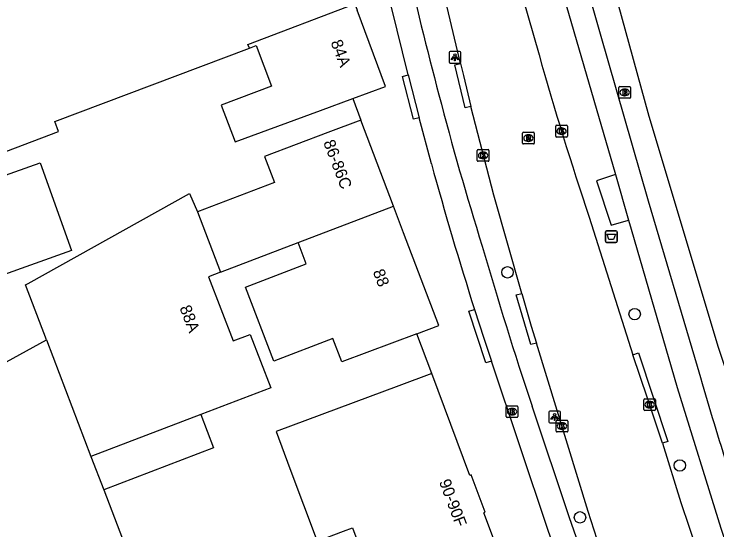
# Model space of a CAD drawing. Extents: x 160026 to 161302, y 384757 to 385701.
# Drawn here: x 160779.8 to 160839.9, y 384906.6 to 384950.7 of the extents above; entities that cross this region are included whole.
import ezdxf

# ---------------------------------------------------------------- set-up
doc = ezdxf.new("R2010")
doc.units = 0
for name, color, linetype in [('IMGEO_Afvalbak', 7, 'Continuous'), ('IMGEO_Boom', 7, 'Continuous'), ('IMGEO_Brandkraan', 7, 'Continuous'), ('IMGEO_Fietspad_open', 7, 'Continuous'), ('IMGEO_Kolk', 7, 'Continuous'), ('IMGEO_Lichtpunt', 7, 'Continuous'), ('IMGEO_Pand', 7, 'Continuous'), ('IMGEO_Pand_nummerreeks', 7, 'Continuous'), ('IMGEO_Rijbaan_lokaal_gesloten', 7, 'Continuous'), ('IMGEO_Rioolput', 7, 'Continuous'), ('IMGEO_Voetpad_gesloten', 7, 'Continuous'), ('IMGEO_Voetpad_open', 7, 'Continuous')]:
    doc.layers.add(name, color=color, linetype=linetype)

msp = doc.modelspace()

# ---------------------------------------------------------------- linework, layer by layer
at = {"layer": 'IMGEO_Afvalbak'}
for p, q in [((160830.469, 384932.145), (160831.259, 384932.145)), ((160831.259, 384932.145), (160830.469, 384932.145)), ((160830.369, 384931.245), (160830.369, 384932.045)), ((160830.369, 384932.045), (160830.369, 384931.245)), ((160831.359, 384932.045), (160831.359, 384931.245)), ((160831.359, 384931.245), (160831.359, 384932.045)), ((160831.259, 384931.145), (160830.469, 384931.145)), ((160830.469, 384931.145), (160831.259, 384931.145))]:
    msp.add_line(p, q, dxfattribs=at)
msp.add_lwpolyline([(160830.512, 384931.859), (160831.216, 384931.859), (160831.067, 384931.389), (160830.661, 384931.389), (160830.512, 384931.859)], dxfattribs=at)
for centre, start, end in [((160830.469, 384932.045), 90, 180), ((160830.469, 384932.045), 90, 180), ((160831.259, 384932.045), 0, 90), ((160831.259, 384932.045), 360, 90), ((160830.469, 384931.245), 180, 270), ((160830.469, 384931.245), 180, 270), ((160831.259, 384931.245), 270, 0), ((160831.259, 384931.245), 270, 0)]:
    msp.add_arc(centre, 0.1, start, end, dxfattribs=at)
at = {"layer": 'IMGEO_Boom'}
for centre in [(160821.994, 384928.592), (160832.87, 384925.019), (160836.726, 384912.075), (160828.191, 384907.632)]:
    msp.add_circle(centre, 0.489, dxfattribs=at)
at = {"layer": 'IMGEO_Brandkraan'}
for p, q in [((160831.513, 384943.548), (160831.513, 384944.4)), ((160831.588, 384944.474), (160832.44, 384944.474)), ((160832.001, 384944.254), (160832.026, 384944.254)), ((160832.514, 384944.4), (160832.514, 384943.548)), ((160832.024, 384943.694), (160831.999, 384943.694)), ((160832.44, 384943.474), (160831.588, 384943.474)), ((160821.884, 384916.248), (160821.884, 384917.1)), ((160821.959, 384917.174), (160822.811, 384917.174)), ((160822.885, 384917.1), (160822.885, 384916.248)), ((160822.372, 384916.954), (160822.397, 384916.954)), ((160822.811, 384916.174), (160821.959, 384916.174)), ((160822.395, 384916.394), (160822.37, 384916.394))]:
    msp.add_line(p, q, dxfattribs=at)
for points in [[(160831.513, 384943.548), (160831.513, 384944.4)], [(160831.588, 384944.474), (160832.44, 384944.474)], [(160831.861, 384944.174), (160831.861, 384943.774), (160832.074, 384943.774)], [(160832.092, 384944.174), (160831.861, 384944.174)], [(160832.514, 384944.4), (160832.514, 384943.548)], [(160832.04, 384944.093), (160831.986, 384944.093), (160831.986, 384944.017)], [(160831.986, 384944.017), (160832.039, 384944.017)], [(160832.048, 384943.941), (160831.986, 384943.941), (160831.986, 384943.86)], [(160831.986, 384943.86), (160832.048, 384943.86)], [(160832.44, 384943.474), (160831.588, 384943.474)], [(160821.884, 384916.248), (160821.884, 384917.1)], [(160821.959, 384917.174), (160822.811, 384917.174)], [(160822.885, 384917.1), (160822.885, 384916.248)], [(160822.232, 384916.874), (160822.232, 384916.474), (160822.445, 384916.474)], [(160822.463, 384916.874), (160822.232, 384916.874)], [(160822.411, 384916.793), (160822.357, 384916.793), (160822.357, 384916.717)], [(160822.357, 384916.717), (160822.41, 384916.717)], [(160822.419, 384916.641), (160822.357, 384916.641), (160822.357, 384916.56)], [(160822.357, 384916.56), (160822.419, 384916.56)], [(160822.811, 384916.174), (160821.959, 384916.174)]]:
    msp.add_lwpolyline(points, dxfattribs=at)
for centre, radius, start, end in [((160831.59, 384944.398), 0.0765, 91.55205, 178.44795), ((160831.59, 384944.398), 0.0765, 91.55205, 178.44795), ((160832.096, 384944.029), 0.145, 59.4692, 91.53667), ((160832.121, 384944.076), 0.0922, 285.51372, 58.15012), ((160832.438, 384944.398), 0.0765, 1.55205, 88.44795), ((160832.438, 384944.398), 0.0765, 1.55205, 88.44795), ((160831.59, 384943.55), 0.0765, 181.55205, 268.44795), ((160831.59, 384943.55), 0.0765, 181.55205, 268.44795), ((160832.041, 384944.055), 0.0379, 267.82845, 90.93552), ((160832.049, 384943.9), 0.0404, 269.87594, 90.50774), ((160832.08, 384944.025), 0.251, 268.66757, 293.53466), ((160832.126, 384943.884), 0.105, 301.31148, 78.98903), ((160832.438, 384943.55), 0.0765, 271.55205, 358.44795), ((160832.438, 384943.55), 0.0765, 271.55205, 358.44795), ((160821.961, 384917.098), 0.0765, 91.55205, 178.44795), ((160821.961, 384917.098), 0.0765, 91.55205, 178.44795), ((160822.809, 384917.098), 0.0765, 1.55205, 88.44795), ((160822.809, 384917.098), 0.0765, 1.55205, 88.44795), ((160822.412, 384916.755), 0.0379, 267.82845, 90.93552), ((160822.42, 384916.6), 0.0404, 269.87594, 90.50774), ((160822.451, 384916.725), 0.251, 268.66757, 293.53466), ((160822.467, 384916.729), 0.145, 59.4692, 91.53667), ((160822.492, 384916.776), 0.0922, 285.51372, 58.15012), ((160822.497, 384916.584), 0.105, 301.31148, 78.98903), ((160821.961, 384916.25), 0.0765, 181.55205, 268.44795), ((160821.961, 384916.25), 0.0765, 181.55205, 268.44795), ((160822.809, 384916.25), 0.0765, 271.55205, 358.44795), ((160822.809, 384916.25), 0.0765, 271.55205, 358.44795)]:
    msp.add_arc(centre, radius, start, end, dxfattribs=at)
for centre, major_axis, ratio, start_param, end_param in [((160832, 384943.974), (-0.387, 0.002), 0.722429, 4.712389, 7.853982), ((160832.025, 384943.974), (-0.39, 0.002), 0.717154, 1.570796, 4.712389), ((160822.371, 384916.674), (-0.387, 0.002), 0.722429, 4.712389, 7.853982), ((160822.396, 384916.674), (-0.39, 0.002), 0.717154, 1.570796, 4.712389)]:
    msp.add_ellipse(centre, major_axis=major_axis, ratio=ratio, start_param=start_param, end_param=end_param, dxfattribs=at)
at = {"layer": 'IMGEO_Fietspad_open'}
for points in [[(160814.194, 385007.048), (160814.986, 385000), (160815.844, 384994.219), (160816.431, 384990.383), (160816.702, 384988.921), (160817.127, 384986.92), (160817.62, 384984.728), (160818.538, 384981.595), (160820.892, 384972.809), (160823.521, 384963.563), (160825.943, 384955.094), (160829.383, 384943.326), (160831.218, 384936.953)], [(160813.512, 384945.476), (160812.075, 384951.268), (160810.742, 384956.99), (160809.406, 384962.711), (160806.711, 384974.852), (160805.938, 384978.422), (160804.898, 384983.229)], [(160822.229, 384975.915), (160826.033, 384962.616), (160829.91, 384948.986), (160834.021, 384934.719), (160838.209, 384920.565)], [(160813.512, 384945.476), (160814.451, 384941.818)], [(160815.496, 384937.862), (160814.451, 384941.818)], [(160831.218, 384936.953), (160832.341, 384933.054)], [(160832.341, 384933.054), (160832.563, 384932.283), (160836.504, 384918.732), (160840.233, 384906.719), (160842.877, 384898.87), (160846.129, 384889.655), (160847.192, 384886.516)], [(160819.177, 384925.414), (160819.968, 384922.959), (160820.618, 384920.998)], [(160826.184, 384904.475), (160825.468, 384906.506), (160820.618, 384920.998)], [(160836.248, 384882.034), (160827.287, 384907.585), (160824.095, 384917.15)]]:
    msp.add_lwpolyline(points, dxfattribs=at)
for centre, radius, start, end in [((161146.831, 385031.365), 342.1, 192.79581, 194.83349), ((161076.974, 385011.413), 269.467, 194.53522, 197.39997), ((161127.862, 385023.463), 323.883, 195.32523, 197.62173), ((161158.101, 385028.576), 352.102, 196.11702, 198.44886), ((161097.911, 384994.45), 270.008, 195.88097, 199.34259)]:
    msp.add_arc(centre, radius, start, end, dxfattribs=at)
at = {"layer": 'IMGEO_Kolk'}
for p, q in [((160826.19, 384941.165), (160827.042, 384941.165)), ((160826.115, 384940.239), (160826.115, 384941.091)), ((160826.603, 384940.945), (160826.628, 384940.945)), ((160827.116, 384941.091), (160827.116, 384940.239)), ((160827.042, 384940.165), (160826.19, 384940.165)), ((160826.626, 384940.385), (160826.601, 384940.385)), ((160819.408, 384938.161), (160819.408, 384939.013)), ((160819.483, 384939.087), (160820.335, 384939.087)), ((160819.896, 384938.867), (160819.921, 384938.867)), ((160820.409, 384939.013), (160820.409, 384938.161)), ((160819.919, 384938.307), (160819.894, 384938.307)), ((160820.335, 384938.087), (160819.483, 384938.087)), ((160833.647, 384916.845), (160833.647, 384917.697)), ((160833.722, 384917.771), (160834.574, 384917.771)), ((160834.648, 384917.697), (160834.648, 384916.845)), ((160834.135, 384917.551), (160834.16, 384917.551)), ((160834.574, 384916.771), (160833.722, 384916.771)), ((160834.158, 384916.991), (160834.133, 384916.991)), ((160826.231, 384915.936), (160827.083, 384915.936)), ((160826.156, 384915.01), (160826.156, 384915.862)), ((160826.644, 384915.716), (160826.669, 384915.716)), ((160827.157, 384915.862), (160827.157, 384915.01)), ((160827.083, 384914.936), (160826.231, 384914.936)), ((160826.667, 384915.156), (160826.642, 384915.156))]:
    msp.add_line(p, q, dxfattribs=at)
for points in [[(160826.19, 384941.165), (160827.042, 384941.165)], [(160826.115, 384940.239), (160826.115, 384941.091)], [(160826.436, 384940.865), (160826.559, 384940.865), (160826.559, 384940.714), (160826.689, 384940.865), (160826.853, 384940.865), (160826.707, 384940.714), (160826.86, 384940.465), (160826.708, 384940.465), (160826.623, 384940.629), (160826.559, 384940.562), (160826.559, 384940.465), (160826.436, 384940.465), (160826.436, 384940.865)], [(160827.116, 384941.091), (160827.116, 384940.239)], [(160827.042, 384940.165), (160826.19, 384940.165)], [(160819.408, 384938.161), (160819.408, 384939.013)], [(160819.483, 384939.087), (160820.335, 384939.087)], [(160819.729, 384938.787), (160819.852, 384938.787), (160819.852, 384938.636), (160819.982, 384938.787), (160820.146, 384938.787), (160820, 384938.636), (160820.153, 384938.387), (160820.001, 384938.387), (160819.916, 384938.551), (160819.852, 384938.484), (160819.852, 384938.387), (160819.729, 384938.387), (160819.729, 384938.787)], [(160820.409, 384939.013), (160820.409, 384938.161)], [(160820.335, 384938.087), (160819.483, 384938.087)], [(160833.647, 384916.845), (160833.647, 384917.697)], [(160833.722, 384917.771), (160834.574, 384917.771)], [(160834.648, 384917.697), (160834.648, 384916.845)], [(160833.968, 384917.471), (160834.091, 384917.471), (160834.091, 384917.32), (160834.221, 384917.471), (160834.385, 384917.471), (160834.239, 384917.32), (160834.392, 384917.071), (160834.24, 384917.071), (160834.155, 384917.235), (160834.091, 384917.168), (160834.091, 384917.071), (160833.968, 384917.071), (160833.968, 384917.471)], [(160834.574, 384916.771), (160833.722, 384916.771)], [(160826.231, 384915.936), (160827.083, 384915.936)], [(160826.156, 384915.01), (160826.156, 384915.862)], [(160826.477, 384915.636), (160826.6, 384915.636), (160826.6, 384915.485), (160826.73, 384915.636), (160826.894, 384915.636), (160826.748, 384915.485), (160826.901, 384915.236), (160826.749, 384915.236), (160826.664, 384915.4), (160826.6, 384915.333), (160826.6, 384915.236), (160826.477, 384915.236), (160826.477, 384915.636)], [(160827.157, 384915.862), (160827.157, 384915.01)], [(160827.083, 384914.936), (160826.231, 384914.936)]]:
    msp.add_lwpolyline(points, dxfattribs=at)
for centre, start, end in [((160826.192, 384941.089), 91.55205, 178.44795), ((160826.192, 384941.089), 91.55205, 178.44795), ((160827.04, 384941.089), 1.55205, 88.44795), ((160827.04, 384941.089), 1.55205, 88.44795), ((160826.192, 384940.241), 181.55205, 268.44795), ((160826.192, 384940.241), 181.55205, 268.44795), ((160827.04, 384940.241), 271.55205, 358.44795), ((160827.04, 384940.241), 271.55205, 358.44795), ((160819.485, 384939.011), 91.55205, 178.44795), ((160819.485, 384939.011), 91.55205, 178.44795), ((160820.333, 384939.011), 1.55205, 88.44795), ((160820.333, 384939.011), 1.55205, 88.44795), ((160819.485, 384938.163), 181.55205, 268.44795), ((160819.485, 384938.163), 181.55205, 268.44795), ((160820.333, 384938.163), 271.55205, 358.44795), ((160820.333, 384938.163), 271.55205, 358.44795), ((160833.724, 384917.695), 91.55205, 178.44795), ((160833.724, 384917.695), 91.55205, 178.44795), ((160834.572, 384917.695), 1.55205, 88.44795), ((160834.572, 384917.695), 1.55205, 88.44795), ((160833.724, 384916.847), 181.55205, 268.44795), ((160833.724, 384916.847), 181.55205, 268.44795), ((160834.572, 384916.847), 271.55205, 358.44795), ((160834.572, 384916.847), 271.55205, 358.44795), ((160826.233, 384915.86), 91.55205, 178.44795), ((160826.233, 384915.86), 91.55205, 178.44795), ((160827.081, 384915.86), 1.55205, 88.44795), ((160827.081, 384915.86), 1.55205, 88.44795), ((160826.233, 384915.012), 181.55205, 268.44795), ((160826.233, 384915.012), 181.55205, 268.44795), ((160827.081, 384915.012), 271.55205, 358.44795), ((160827.081, 384915.012), 271.55205, 358.44795)]:
    msp.add_arc(centre, 0.0765, start, end, dxfattribs=at)
for centre, major_axis, ratio, start_param, end_param in [((160826.602, 384940.665), (-0.387, 0.002), 0.722429, 4.712389, 7.853982), ((160826.627, 384940.665), (-0.39, 0.002), 0.717154, 1.570796, 4.712389), ((160819.895, 384938.587), (-0.387, 0.002), 0.722429, 4.712389, 7.853982), ((160819.92, 384938.587), (-0.39, 0.002), 0.717154, 1.570796, 4.712389), ((160834.134, 384917.271), (-0.387, 0.002), 0.722429, 4.712389, 7.853982), ((160834.159, 384917.271), (-0.39, 0.002), 0.717154, 1.570796, 4.712389), ((160826.643, 384915.436), (-0.387, 0.002), 0.722429, 4.712389, 7.853982), ((160826.668, 384915.436), (-0.39, 0.002), 0.717154, 1.570796, 4.712389)]:
    msp.add_ellipse(centre, major_axis=major_axis, ratio=ratio, start_param=start_param, end_param=end_param, dxfattribs=at)
at = {"layer": 'IMGEO_Lichtpunt'}
for p, q in [((160816.998, 384947.387), (160816.998, 384946.58)), ((160816.998, 384947.387), (160816.998, 384946.58)), ((160817.9, 384947.482), (160817.092, 384947.482)), ((160817.9, 384947.482), (160817.092, 384947.482)), ((160817.994, 384946.58), (160817.994, 384947.387)), ((160817.994, 384946.58), (160817.994, 384947.387)), ((160817.092, 384946.486), (160817.9, 384946.486)), ((160817.092, 384946.486), (160817.9, 384946.486)), ((160825.525, 384916.617), (160825.525, 384915.81)), ((160825.525, 384916.617), (160825.525, 384915.81)), ((160826.427, 384916.712), (160825.619, 384916.712)), ((160826.427, 384916.712), (160825.619, 384916.712)), ((160826.521, 384915.81), (160826.521, 384916.617)), ((160826.521, 384915.81), (160826.521, 384916.617)), ((160825.619, 384915.716), (160826.427, 384915.716)), ((160825.619, 384915.716), (160826.427, 384915.716))]:
    msp.add_line(p, q, dxfattribs=at)
for points in [[(160817.372, 384947.051), (160817.411, 384947.023), (160817.223, 384946.761), (160817.185, 384946.788), (160817.372, 384947.051)], [(160817.474, 384947.003), (160817.521, 384947.003), (160817.521, 384946.681), (160817.474, 384946.681), (160817.474, 384947.003)], [(160817.584, 384947.023), (160817.622, 384947.05), (160817.809, 384946.788), (160817.77, 384946.76), (160817.584, 384947.023)], [(160825.899, 384916.281), (160825.938, 384916.253), (160825.75, 384915.991), (160825.712, 384916.018), (160825.899, 384916.281)], [(160826.001, 384916.233), (160826.048, 384916.233), (160826.048, 384915.911), (160826.001, 384915.911), (160826.001, 384916.233)], [(160826.111, 384916.253), (160826.149, 384916.28), (160826.336, 384916.018), (160826.297, 384915.99), (160826.111, 384916.253)]]:
    msp.add_lwpolyline(points, dxfattribs=at)
for centre in [(160817.497, 384947.185), (160826.024, 384916.415)]:
    msp.add_circle(centre, 0.0994, dxfattribs=at)
for centre, start, end in [((160817.092, 384947.387), 90, 180), ((160817.092, 384947.387), 90, 180), ((160817.9, 384947.387), 0, 90), ((160817.9, 384947.387), 0, 90), ((160817.092, 384946.58), 180, 270), ((160817.092, 384946.58), 180, 270), ((160817.9, 384946.58), 270, 0), ((160817.9, 384946.58), 270, 360), ((160825.619, 384916.617), 90, 180), ((160825.619, 384916.617), 90, 180), ((160826.427, 384916.617), 0, 90), ((160826.427, 384916.617), 0, 90), ((160825.619, 384915.81), 180, 270), ((160825.619, 384915.81), 180, 270), ((160826.427, 384915.81), 270, 0), ((160826.427, 384915.81), 270, 360)]:
    msp.add_arc(centre, 0.0946, start, end, dxfattribs=at)
at = {"layer": 'IMGEO_Pand'}
for points in [[(160771.783, 384953.899), (160777.651, 384938.371), (160783.627, 384940.629), (160783.304, 384941.484), (160799.934, 384947.768)], [(160799.934, 384947.768), (160799.812, 384948.089), (160808.95, 384951.552), (160809.153, 384951.006)], [(160808.778, 384943.448), (160811.572, 384944.473), (160809.153, 384951.006)], [(160784.732, 384930.464), (160775.379, 384927.123), (160776.271, 384924.625), (160770.071, 384922.41), (160767.954, 384928.339), (160771.72, 384929.683), (160767.746, 384940.812), (160765.85, 384940.135), (160763.339, 384947.165), (160772.272, 384950.355), (160777.301, 384936.272), (160782.051, 384937.969), (160784.732, 384930.464)], [(160799.934, 384947.768), (160800.498, 384947.981), (160801.811, 384944.506), (160797.519, 384942.884), (160798.704, 384939.75), (160806.014, 384942.433), (160808.778, 384943.448)], [(160809.45, 384941.617), (160806.645, 384940.552), (160801.225, 384938.495), (160802.073, 384936.28), (160795.485, 384933.758)], [(160812.244, 384934.258), (160809.45, 384941.617)], [(160782.595, 384922.812), (160780.796, 384927.511), (160781.023, 384927.638), (160794.809, 384935.33), (160795.485, 384933.758)], [(160804.091, 384931.137), (160812.244, 384934.258)], [(160814.255, 384923.336), (160816.12, 384924.031), (160813.115, 384931.963), (160812.244, 384934.258)], [(160795.485, 384933.758), (160797.46, 384928.598)], [(160797.46, 384928.598), (160804.091, 384931.137)], [(160814.255, 384923.336), (160807.832, 384920.943), (160807.071, 384922.93), (160802.018, 384920.996), (160799.597, 384927.319), (160804.791, 384929.308), (160804.091, 384931.137)], [(160797.46, 384928.598), (160796.441, 384928.208), (160798.542, 384922.722), (160800.004, 384923.282), (160801.754, 384918.71), (160795.775, 384916.421)], [(160788.586, 384888.745), (160779.859, 384885.441), (160779.549, 384886.257), (160771.521, 384883.201), (160771.642, 384882.873), (160771.014, 384882.635), (160770.893, 384882.963), (160764.6, 384880.569), (160766.456, 384875.692), (160741.042, 384870.459), (160736.144, 384869.451), (160733.533, 384882.133), (160738.872, 384883.188), (160742.841, 384883.972), (160743.29, 384881.699), (160757.729, 384884.553), (160757.227, 384887.095), (160762.126, 384888.063), (160755.507, 384907.922), (160782.595, 384922.812)], [(160782.595, 384922.812), (160786.39, 384912.828)], [(160815.524, 384919.931), (160812.713, 384918.884), (160802.213, 384914.97), (160803.403, 384911.801), (160805.732, 384905.602), (160807.983, 384906.447), (160808.744, 384906.732), (160809.604, 384904.441), (160811.169, 384905.028), (160813.355, 384899.204), (160818.316, 384901.072), (160822.06, 384902.482)], [(160822.06, 384902.482), (160819.974, 384908.019), (160820.096, 384908.065), (160818.895, 384911.258), (160818.774, 384911.213), (160815.524, 384919.931)], [(160795.775, 384916.421), (160786.39, 384912.828)], [(160795.775, 384916.421), (160796.865, 384913.576), (160787.477, 384909.982)], [(160786.39, 384912.828), (160787.477, 384909.982)], [(160787.477, 384909.982), (160790.532, 384901.978), (160794.298, 384890.791)]]:
    msp.add_lwpolyline(points, dxfattribs=at)
at = {"layer": 'IMGEO_Rijbaan_lokaal_gesloten'}
for points in [[(160817.988, 384946.446), (160815.198, 384958.281), (160813.233, 384967.812), (160812.245, 384973.269), (160811.828, 384975.767)], [(160821.935, 384957.322), (160822.829, 384953.761), (160824.696, 384947.188)], [(160817.988, 384946.446), (160818.232, 384945.425), (160818.854, 384942.786)], [(160823.218, 384926.793), (160820.825, 384935.189), (160818.854, 384942.786)], [(160828.989, 384933.312), (160832.71, 384921.54)], [(160823.218, 384926.793), (160824.03, 384923.982), (160824.472, 384922.545)], [(160829.663, 384905.732), (160828.903, 384908.123), (160824.472, 384922.545)], [(160835.238, 384913.97), (160833.95, 384917.829), (160832.71, 384921.54)], [(160835.238, 384913.97), (160836.816, 384908.917), (160838.236, 384904.691), (160842.513, 384894.011)]]:
    msp.add_lwpolyline(points, dxfattribs=at)
msp.add_arc((161092.74, 385022.514), 278.428, 195.69652, 198.68585, dxfattribs=at)
at = {"layer": 'IMGEO_Rioolput'}
for p, q in [((160823.359, 384940.568), (160824.211, 384940.568)), ((160823.284, 384939.642), (160823.284, 384940.494)), ((160823.772, 384940.348), (160823.797, 384940.348)), ((160824.285, 384940.494), (160824.285, 384939.642)), ((160824.211, 384939.568), (160823.359, 384939.568)), ((160823.795, 384939.788), (160823.77, 384939.788))]:
    msp.add_line(p, q, dxfattribs=at)
for points in [[(160823.359, 384940.568), (160824.211, 384940.568)], [(160823.284, 384939.642), (160823.284, 384940.494)], [(160823.873, 384940.266), (160823.621, 384940.268), (160823.621, 384939.868)], [(160823.621, 384939.868), (160823.745, 384939.868), (160823.745, 384940.03), (160823.756, 384940.03)], [(160823.799, 384940.187), (160823.745, 384940.187), (160823.745, 384940.106)], [(160823.745, 384940.106), (160823.797, 384940.106)], [(160823.803, 384940.001), (160823.874, 384939.868), (160824.014, 384939.868), (160823.949, 384939.994)], [(160824.285, 384940.494), (160824.285, 384939.642)], [(160824.211, 384939.568), (160823.359, 384939.568)]]:
    msp.add_lwpolyline(points, dxfattribs=at)
for centre, radius, start, end in [((160823.361, 384940.492), 0.0765, 91.55205, 178.44795), ((160823.361, 384940.492), 0.0765, 91.55205, 178.44795), ((160824.209, 384940.492), 0.0765, 1.55205, 88.44795), ((160824.209, 384940.492), 0.0765, 1.55205, 88.44795), ((160823.755, 384939.977), 0.0533, 26.02933, 88.69889), ((160823.781, 384940.295), 0.19, 274.7715, 282.96867), ((160823.805, 384940.091), 0.0964, 77.00612, 93.18647), ((160823.819, 384940.148), 0.0378, 276.66336, 79.67722), ((160823.872, 384940.156), 0.109, 350.36119, 89.41601), ((160823.87, 384940.156), 0.112, 277.58423, 350.98172), ((160823.854, 384939.941), 0.108, 29.51342, 73.79051), ((160823.361, 384939.644), 0.0765, 181.55205, 268.44795), ((160823.361, 384939.644), 0.0765, 181.55205, 268.44795), ((160824.209, 384939.644), 0.0765, 271.55205, 358.44795), ((160824.209, 384939.644), 0.0765, 271.55205, 358.44795)]:
    msp.add_arc(centre, radius, start, end, dxfattribs=at)
for centre, major_axis, ratio, start_param, end_param in [((160823.771, 384940.068), (-0.387, 0.002), 0.722429, 4.712389, 7.853982), ((160823.796, 384940.068), (-0.39, 0.002), 0.717154, 1.570796, 4.712389)]:
    msp.add_ellipse(centre, major_axis=major_axis, ratio=ratio, start_param=start_param, end_param=end_param, dxfattribs=at)
at = {"layer": 'IMGEO_Voetpad_gesloten'}
msp.add_lwpolyline([(160831.218, 384936.953), (160829.617, 384936.429), (160830.861, 384932.627), (160832.341, 384933.054)], dxfattribs=at)
at = {"layer": 'IMGEO_Voetpad_open'}
for points in [[(160825.406, 384972.674), (160825.488, 384972.415), (160825.57, 384972.156), (160830.052, 384956.59), (160834.068, 384941.96), (160840.01, 384922.194), (160845.037, 384906.959), (160851.684, 384888.467), (160853.379, 384883.752)], [(160818.854, 384942.786), (160818.368, 384942.672), (160817.502, 384946.332), (160817.988, 384946.446)], [(160814.451, 384941.818), (160813.968, 384941.694), (160813.028, 384945.352), (160813.512, 384945.476)], [(160808.778, 384943.448), (160809.45, 384941.617)], [(160824.472, 384922.545), (160823.993, 384922.405), (160822.74, 384926.653), (160823.218, 384926.793)], [(160820.618, 384920.998), (160820.143, 384920.845), (160818.702, 384925.261), (160819.177, 384925.414)], [(160815.524, 384919.931), (160814.255, 384923.336)], [(160832.71, 384921.54), (160833.184, 384921.697), (160835.712, 384914.127), (160835.238, 384913.97)]]:
    msp.add_lwpolyline(points, dxfattribs=at)

# ---------------------------------------------------------------- texts
at = {"layer": 'IMGEO_Pand_nummerreeks'}
for s, rotation, p in [('84A', 290.71221, (160806.863, 384948.27)), ('86-86C', 290.95286, (160806.232, 384939.708)), ('88', 290.95286, (160810.468, 384928.646)), ('88A', 290.95286, (160793.943, 384925.558)), ('90-90F', 290.58616, (160816.127, 384910.683))]:
    msp.add_text(s, height=1, rotation=rotation, dxfattribs=at).set_placement(p)

doc.saveas('drawing.dxf')
